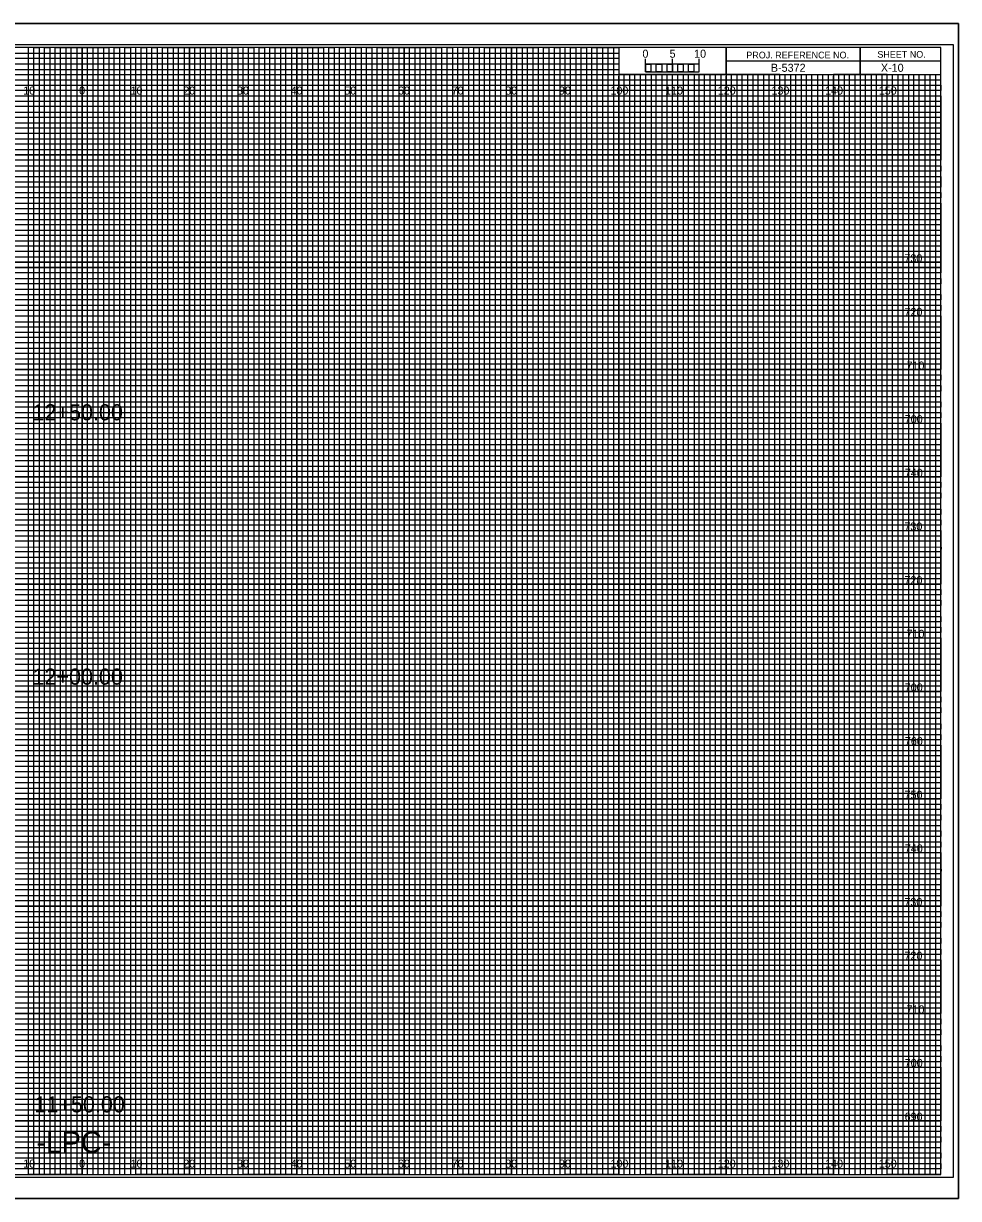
# Model space of a CAD drawing. Extents: x -397 to 323, y -4 to 654.
# Drawn here: x 149.1 to 323.3, y 215.5 to 434.5 of the extents above; entities that cross this region are included whole.
import ezdxf

# ---------------------------------------------------------------- set-up
doc = ezdxf.new("R2010")
doc.units = 0
for name, color, linetype in [('Default', 7, 'Continuous'), ('Prop XS Alignment Label', 7, 'Continuous'), ('Prop XS Bar Scale Labels', 7, 'Continuous'), ('Prop XS Elevation Labels', 7, 'Continuous'), ('Prop XS Offset Labels', 7, 'Continuous'), ('Prop XS Project Number', 7, 'Continuous'), ('Prop XS Sheet Number', 7, 'Continuous'), ('Prop XS Station Labels', 7, 'Continuous'), ('Sheet Cross Section CELL', 7, 'Continuous'), ('Sheet Cross Section Grid Major CELL', 7, 'Continuous'), ('Sheet Cross Section Grid Middle CELL', 7, 'Continuous'), ('Sheet Cross Section Grid Minor 1 CELL', 7, 'Continuous'), ('Sheet Cross Section Grid Minor 2 CELL', 7, 'Continuous'), ('Sheet Cross Section Scale CELL', 7, 'Continuous'), ('Sheet Cutting Line CELL', 7, 'Continuous'), ('Sheet DOT Grid CELL', 7, 'Continuous'), ('Sheet Plot Border Inside CELL', 7, 'Continuous'), ('Sheet Plot Border Outside CELL', 7, 'Continuous')]:
    doc.layers.add(name, color=color, linetype=linetype)

msp = doc.modelspace()

# ---------------------------------------------------------------- linework, layer by layer
at = {"layer": 'Default'}
msp.add_lwpolyline([(323.3, 215.5), (-13.4, 215.5), (-13.4, 434.5), (323.3, 434.5)], close=True, dxfattribs=at)
at = {"layer": 'Sheet Cross Section CELL'}
for p, q in [((305, 430), (305, 425)), ((305, 425), (305, 430)), ((280, 427.5), (280, 425)), ((320, 427.49), (280, 427.49)), ((280, 425), (320, 425))]:
    msp.add_line(p, q, dxfattribs=at)
for points in [[(320, 430), (0, 430), (0, 220), (320, 220)], [(280, 430), (260, 430), (260, 425.03), (280, 425.03)], [(320, 430), (280, 430), (280, 425), (320, 425)]]:
    msp.add_lwpolyline(points, close=True, dxfattribs=at)
at = {"layer": 'Sheet Cross Section Grid Major CELL'}
for p, q in [((150, 430), (140, 430)), ((150, 220), (150, 430)), ((170, 430), (160, 430)), ((160, 430), (160, 220)), ((170, 220), (170, 430)), ((190, 430), (180, 430)), ((180, 430), (180, 220)), ((190, 220), (190, 430)), ((210, 430), (200, 430)), ((200, 430), (200, 220)), ((210, 220), (210, 430)), ((230, 430), (220, 430)), ((220, 430), (220, 220)), ((230, 220), (230, 430)), ((250, 430), (240, 430)), ((240, 430), (240, 220)), ((250, 220), (250, 430)), ((260, 430), (260, 220)), ((270, 220), (270, 425)), ((290, 425), (280, 425)), ((280, 425), (280, 220)), ((290, 220), (290, 425)), ((310, 425), (300, 425)), ((300, 425), (300, 220)), ((310, 220), (310, 425)), ((160, 220), (150, 220)), ((180, 220), (170, 220)), ((200, 220), (190, 220)), ((220, 220), (210, 220)), ((240, 220), (230, 220)), ((260, 220), (250, 220)), ((280, 220), (270, 220)), ((300, 220), (290, 220)), ((320, 220), (310, 220)), ((320, 220), (320, 220))]:
    msp.add_line(p, q, dxfattribs=at)
for points in [[(0, 420), (320, 420), (320, 410), (0, 410)], [(0, 400), (320, 400), (320, 390), (0, 390)], [(0, 380), (320, 380), (320, 370), (0, 370)], [(0, 360), (320, 360), (320, 350), (0, 350)], [(0, 340), (320, 340), (320, 330), (0, 330)], [(0, 320), (320, 320), (320, 310), (0, 310)], [(0, 300), (320, 300), (320, 290), (0, 290)], [(0, 280), (320, 280), (320, 270), (0, 270)], [(0, 260), (320, 260), (320, 250), (0, 250)], [(0, 240), (320, 240), (320, 230), (0, 230)]]:
    msp.add_lwpolyline(points, dxfattribs=at)
at = {"layer": 'Sheet Cross Section Grid Middle CELL'}
for points in [[(145, 220), (155, 220), (155, 430), (165, 430), (165, 220), (175, 220), (175, 430), (185, 430), (185, 220), (195, 220), (195, 430), (205, 430), (205, 220), (215, 220), (215, 430), (225, 430), (225, 220), (235, 220), (235, 430), (245, 430), (245, 220), (255, 220), (255, 430), (259.93, 430), (260, 430), (260, 425), (264.99, 425), (264.99, 220), (275, 220), (275, 425), (285, 425), (285, 220), (295, 220), (295, 425), (305, 425), (305, 220), (315, 220), (315, 425)], [(0, 425), (275, 425)], [(0, 405), (320, 405), (320, 415), (0, 415)], [(0, 385), (320, 385), (320, 395), (0, 395)], [(0, 365), (320, 365), (320, 375), (0, 375)], [(0, 345), (320, 345), (320, 355), (0, 355)], [(0, 325), (320, 325), (320, 335), (0, 335)], [(0, 305), (320, 305), (320, 315), (0, 315)], [(0, 285), (320, 285), (320, 295), (0, 295)], [(0, 265), (320, 265), (320, 275), (0, 275)], [(0, 245), (320, 245), (320, 255), (0, 255)], [(0, 225), (320, 225), (320, 235), (0, 235)]]:
    msp.add_lwpolyline(points, dxfattribs=at)
at = {"layer": 'Sheet Cross Section Grid Minor 1 CELL'}
for p, q in [((0, 429), (260, 429)), ((260, 427.98), (0, 427.98)), ((260, 429), (260, 427.98)), ((0, 427), (260, 427)), ((260, 425.89), (0, 425.89)), ((260, 427), (260, 425.89)), ((0, 424), (320, 424))]:
    msp.add_line(p, q, dxfattribs=at)
for points in [[(0, 423), (270, 423), (320, 423), (320, 422), (0, 422)], [(0, 421), (320, 421), (320, 419), (0, 419)], [(0, 418), (320, 418), (320, 417), (0, 416.98)], [(0, 416), (320, 416), (320, 414), (0, 414)], [(0, 413), (320, 413), (320, 412), (0, 412)], [(0, 411), (320, 411), (320, 409), (0, 409)], [(0, 408), (320, 408), (320, 407), (0, 407)], [(0, 406), (320, 406), (320, 404), (0, 404)], [(0, 403), (320, 403), (320, 402), (0, 402)], [(0, 401), (320, 401), (320, 399), (0, 399)], [(0, 398), (320, 398), (320, 397), (0, 397)], [(0, 396), (320, 396), (320, 393.95), (320, 393), (320, 392), (0, 392)], [(0, 394), (320, 394), (320, 393), (0, 393)], [(0, 391), (320, 391), (320, 389), (0, 389.03)], [(0, 389.03), (320, 389), (320, 388), (0, 388)], [(0, 387), (320, 387), (320, 386), (0, 386)], [(0, 384), (320, 384), (320, 383), (0, 383)], [(0, 382), (320, 382), (320, 381), (0, 381)], [(-0.07, 378.89), (320, 378.89), (320, 377.88), (-0.07, 377.88)], [(0, 377), (320, 377), (320, 376), (0, 376)], [(0, 374), (320, 374), (320, 373), (0, 373)], [(0, 372), (320, 372), (320, 371), (0, 371)], [(0, 369), (320, 369), (320, 368), (0, 368)], [(0, 367), (320, 367), (320, 366), (0, 366)], [(0, 364), (320, 364), (320, 363), (0, 363)], [(0, 362), (320, 362), (320, 361), (0, 361)], [(0, 359), (320, 359), (319.99, 357.98), (0, 358)], [(0, 357), (320, 357), (320, 356), (0, 356)], [(0, 354), (320, 354), (320, 353), (0, 353)], [(0, 352), (320, 352), (320, 351), (0, 351)], [(0, 349), (320, 349), (320, 348), (0, 348)], [(0, 347), (320, 347), (320, 346), (0, 346)], [(0, 344), (320, 344), (320, 343), (0, 343)], [(0, 342), (320, 342), (320, 341), (0, 341)], [(0, 339), (320, 339), (320, 338), (0, 338)], [(0, 336.99), (320.07, 336.91), (320, 336), (0, 336)], [(0, 334), (320, 334), (320, 333), (0, 333)], [(0, 332), (320, 332), (320, 331), (0, 331)], [(0, 329), (320, 329), (320, 328), (0, 328)], [(0, 327), (320, 327), (320, 326), (0, 326)], [(0, 324), (320, 324), (320, 323), (0, 323)], [(0, 322), (320, 322), (320, 321), (0, 321)], [(0, 319), (320, 319), (320, 318), (0, 318)], [(0, 317), (320, 317), (320, 316), (0, 316)], [(0, 314), (320, 314), (320, 313), (0, 313)], [(0, 312), (320, 312), (320, 311), (0, 311)], [(0, 309), (320, 309), (320, 308), (0, 308)], [(0, 307), (320, 307), (320, 306), (0, 306)], [(0, 304), (320, 304), (320, 303), (0, 303)], [(0, 302), (320, 302), (320, 301), (0, 301)], [(0, 299), (320, 299), (319.99, 297.98), (0, 298)], [(0, 297), (320, 297), (320, 296), (0, 296)], [(0, 294), (320, 294), (320, 293), (0, 293)], [(0, 292), (320, 292), (320, 291), (0, 291)], [(0, 289), (320, 289), (320, 288), (0, 288)], [(0, 287), (320, 287), (320, 286), (0, 286)], [(0, 284), (320, 284), (320, 283), (0, 283)], [(0, 282), (320, 282), (320, 281), (0, 281)], [(0, 279), (320, 279), (320, 278), (0, 278)], [(0, 276.99), (320.07, 276.91), (320, 276), (0, 276)], [(0, 274), (320, 274), (320, 273), (0, 273)], [(0, 272), (320, 272), (320, 271), (0, 271)], [(0, 269), (320, 269), (320, 268), (0, 268)], [(0, 267), (320, 267), (320, 266), (0, 266)], [(0, 264), (320, 264), (320, 263), (0, 263)], [(0, 262), (320, 262), (320, 261), (0, 261)], [(0, 259), (320, 259), (320, 258), (0, 258)], [(0, 257), (320, 257), (320, 256), (0, 256)], [(0, 254), (320, 254), (320, 253), (0, 253)], [(0, 252), (320, 252), (320, 251), (0, 251)], [(0, 249), (320, 249), (320, 248), (0, 248)], [(0, 247), (320, 247), (320, 246), (0, 246)], [(0, 244), (320, 244), (320, 243), (0, 243)], [(0, 242), (320, 242), (320, 241), (0, 241)], [(0, 239), (320, 239), (320, 238), (0, 238)], [(0, 237), (320, 237), (320, 236), (0, 236)], [(0, 234), (320, 234), (320, 233), (0, 233)], [(0, 232), (320, 232), (320, 231), (0, 231)], [(0, 229), (320, 229), (320, 228), (0, 228)], [(0, 227), (320, 227), (320, 226), (0, 226)], [(0, 224), (320, 224), (320, 223), (0, 223)], [(0, 222), (320, 222), (320, 221), (0, 221)]]:
    msp.add_lwpolyline(points, dxfattribs=at)
at = {"layer": 'Sheet Cross Section Grid Minor 2 CELL'}
for p, q in [((267, 425), (266.01, 425)), ((266.01, 425), (266.01, 220)), ((267, 220), (267, 425)), ((269, 425), (268, 425)), ((268, 425), (268, 220)), ((269, 220), (269, 425)), ((266.01, 220), (265, 220)), ((268, 220), (267, 220))]:
    msp.add_line(p, q, dxfattribs=at)
for points in [[(150, 220), (151, 220), (151, 430), (152, 430), (152, 220)], [(152, 220), (153, 220), (153, 430), (154, 430), (154, 220)], [(155, 220), (156, 220), (156, 430), (157, 430), (157, 220)], [(157, 220), (158, 220), (158, 430), (159, 430), (159, 220)], [(160, 220), (161, 220), (161, 430), (162, 430), (162, 220)], [(162, 220), (163, 220), (163, 430), (164, 430), (164, 220)], [(165, 220), (166, 220), (166, 430), (167, 430), (167, 220)], [(167, 220), (168, 220), (168, 430), (169, 430), (169, 220)], [(170, 220), (171, 220), (171, 430), (172, 430), (172, 220)], [(172, 220), (173, 220), (173, 430), (174, 430), (174, 220)], [(175, 220), (176, 220), (176, 430), (177, 430), (177, 220)], [(177, 220), (178, 220), (178, 430), (179, 430), (179, 220)], [(180, 220), (181, 220), (181, 430), (182, 430), (182, 220)], [(182, 220), (183, 220), (183, 430), (184, 430), (184, 220)], [(185, 220), (186, 220), (186, 430), (187, 430), (187, 220)], [(187, 220), (188, 220), (188, 430), (189, 430), (189, 220)], [(190, 220), (191, 220), (191, 430), (192, 430), (192, 220)], [(192, 220), (193, 220), (193, 430), (194, 430), (194, 220)], [(195, 220), (196, 220), (196, 430), (197, 430), (197, 220)], [(197, 220), (198, 220), (198, 430), (199, 430), (199, 220)], [(200, 220), (201, 220), (201, 430), (202, 430), (202, 220)], [(202, 220), (203, 220), (203, 430), (204, 430), (204, 220)], [(205, 220), (206, 220), (206, 430), (207, 430), (207, 220)], [(207, 220), (208, 220), (208, 430), (209, 430), (209, 220)], [(210, 220), (211, 220), (211, 430), (212, 430), (212, 220)], [(212, 220), (213, 220), (213, 430), (214, 430), (214, 220)], [(215, 220), (216, 220), (216, 430), (217, 430), (217, 220)], [(217, 220), (218, 220), (218, 430), (219, 430), (219, 220)], [(220, 220), (221, 220), (221, 430), (222, 430), (222, 220)], [(222, 220), (223, 220), (223, 430), (224, 430), (224, 220)], [(225, 220), (226, 220), (226, 430), (227, 430), (227, 220)], [(227, 220), (228, 220), (228, 430), (229, 430), (229, 220)], [(230, 220), (231, 220), (231, 430), (232, 430), (232, 220)], [(232, 220), (233, 220), (233, 430), (234, 430), (234, 220)], [(235, 220), (236, 220), (236, 430), (237, 430), (237, 220)], [(237, 220), (238, 220), (238, 430), (239, 430), (239, 220)], [(240, 220), (241, 220), (241, 430), (242, 430), (242, 220)], [(242, 220), (243, 220), (243, 430), (244, 430), (244, 220)], [(245, 220), (246, 220), (246, 430), (247, 430), (247, 220)], [(247, 220), (248, 220), (248, 430), (249, 430), (249, 220)], [(250, 220), (251, 220), (251, 430), (252, 430), (252, 220)], [(252, 220), (253, 220), (253, 430), (254, 430), (254, 220)], [(255, 220), (256, 220), (256, 430), (257, 430), (257, 220)], [(257, 220), (258, 220), (258, 430), (259, 430), (259, 220)], [(260, 220), (261, 220), (261, 425), (262.02, 425), (262.02, 220)], [(262, 220), (263, 220), (263, 425), (263.99, 425), (263.99, 220)], [(270, 220), (270.98, 220), (270.98, 425), (272, 425), (272, 220)], [(272, 220), (273, 220), (273, 425), (274.05, 425), (274.05, 220)], [(275, 220), (276, 220), (276, 425), (277, 425), (277, 220)], [(277, 220), (278, 220), (278, 425), (279, 425), (279, 220)], [(280, 220), (281, 220), (281, 425), (282, 425), (282, 220)], [(282, 220), (283, 220), (283, 425), (284, 425), (284, 220)], [(285, 220), (286, 220), (286, 425), (287, 425), (287, 220)], [(287, 220), (288, 220), (288, 425), (289, 425), (289, 220)], [(290, 220), (291, 220), (291, 425), (292, 425), (292, 220)], [(292, 220), (293, 220), (293, 425), (294, 425), (294, 220)], [(295, 220), (296, 220), (296, 425), (297, 425), (297, 220)], [(297, 220), (298, 220), (298, 425), (299, 425), (299, 220)], [(300, 220), (301, 220), (301, 425), (302, 425), (302, 220)], [(302, 220), (303, 220), (303, 425), (304, 425), (304, 220)], [(305, 220), (306, 220), (306, 425), (307, 425), (307, 220)], [(307, 220), (308, 220), (308, 425), (309, 425), (309, 220)], [(310, 220), (311, 220), (311, 425), (312, 425), (312, 220)], [(312, 220), (313, 220), (313, 425), (314, 425), (314, 220)], [(315, 220), (316, 220), (316, 425), (317, 425), (317, 220)], [(317, 220), (318, 220), (318, 425), (319, 425), (319, 220)]]:
    msp.add_lwpolyline(points, dxfattribs=at)
at = {"layer": 'Sheet Cross Section Scale CELL'}
for p, q in [((265, 425.49), (265, 427.9)), ((265, 426.9), (265, 427.9)), ((270, 425.49), (270, 427.9)), ((275, 425.49), (275, 427.9)), ((275, 426.9), (275, 427.9))]:
    msp.add_line(p, q, dxfattribs=at)
for points in [[(275, 426.9), (265, 426.9), (265, 425.49), (275, 425.49)], [(265, 426.9), (266, 426.9), (266, 425.49), (265, 425.49)], [(267, 426.9), (268, 426.9), (268, 425.49), (267, 425.49)], [(269, 426.9), (270, 426.9), (270, 425.49), (269, 425.49)], [(271, 426.9), (272, 426.9), (272, 425.49), (271, 425.49)], [(273, 426.9), (274, 426.9), (274, 425.49), (273, 425.49)]]:
    msp.add_lwpolyline(points, close=True, dxfattribs=at)
at = {"layer": 'Sheet Cutting Line CELL'}
for p, q in [((323.3, 434.5), (-13.4, 434.5)), ((-13.4, 215.5), (323.3, 215.5))]:
    msp.add_line(p, q, dxfattribs=at)
at = {"layer": 'Sheet DOT Grid CELL'}
for p, q in [((150, 220), (150, 430)), ((160, 220), (160, 430)), ((170, 220), (170, 430)), ((180, 220), (180, 430)), ((190, 220), (190, 430)), ((200, 220), (200, 430)), ((210, 220), (210, 430)), ((220, 220), (220, 430)), ((230, 220), (230, 430)), ((240, 220), (240, 430)), ((250, 220), (250, 430)), ((260, 220), (260, 424.69)), ((270, 220), (270, 424.69)), ((280, 220), (280, 424.69)), ((290, 220), (290, 424.69)), ((300, 220), (300, 424.69)), ((310, 220), (310, 424.69)), ((0, 420), (320, 420)), ((0, 410), (320, 410)), ((0, 400), (320, 400)), ((0, 390), (320, 390)), ((0, 380), (320, 380)), ((0, 370), (320, 370)), ((0, 360), (320, 360)), ((0, 350), (320, 350)), ((0, 340), (320, 340)), ((0, 330), (320, 330)), ((0, 320), (320, 320)), ((0, 310), (320, 310)), ((0, 300), (320, 300)), ((0, 290), (320, 290)), ((0, 280), (320, 280)), ((0, 270), (320, 270)), ((0, 260), (320, 260)), ((0, 250), (320, 250)), ((0, 240), (320, 240)), ((0, 230), (320, 230))]:
    msp.add_line(p, q, dxfattribs=at)
at = {"layer": 'Sheet Plot Border Inside CELL'}
msp.add_lwpolyline([(-10.8, 219.5), (322.4, 219.5), (322.4, 430.5), (-10.8, 430.5)], close=True, dxfattribs=at)
at = {"layer": 'Sheet Plot Border Outside CELL'}
msp.add_lwpolyline([(-13.4, 215.5), (323.3, 215.5), (323.3, 434.5), (-13.4, 434.5)], close=True, dxfattribs=at)

# ---------------------------------------------------------------- texts
at = {"layer": 'Prop XS Alignment Label'}
msp.add_text('-LPC-', height=4, dxfattribs=at).set_placement((151.47, 224))
at = {"layer": 'Prop XS Bar Scale Labels'}
for s, p in [('5', (269.47, 428.12)), ('10', (274.04, 428.12))]:
    msp.add_text(s, height=1.5, dxfattribs=at).set_placement(p)
at = {"layer": 'Prop XS Elevation Labels'}
for s, p in [('730', (313.22, 390)), ('720', (313.23, 380)), ('710', (313.61, 370)), ('700', (313.28, 360)), ('740', (313.3, 350)), ('730', (313.22, 340)), ('720', (313.23, 330)), ('710', (313.61, 320)), ('700', (313.28, 310)), ('760', (313.3, 300)), ('750', (313.25, 290)), ('740', (313.3, 280)), ('730', (313.22, 270)), ('720', (313.23, 260)), ('710', (313.61, 250)), ('700', (313.28, 240)), ('690', (313.26, 230))]:
    msp.add_text(s, height=1.5, dxfattribs=at).set_placement(p)
at = {"layer": 'Prop XS Offset Labels'}
for s, p in [('10', (149.04, 421.25)), ('0', (159.45, 421.25)), ('0', (159.45, 421.25)), ('10', (169.04, 421.25)), ('20', (178.86, 421.25)), ('30', (188.86, 421.25)), ('40', (198.86, 421.25)), ('50', (208.86, 421.25)), ('60', (218.86, 421.25)), ('70', (228.86, 421.25)), ('80', (238.86, 421.25)), ('90', (248.86, 421.25)), ('100', (258.44, 421.25)), ('110', (268.62, 421.25)), ('120', (278.44, 421.25)), ('130', (288.44, 421.25)), ('140', (298.44, 421.25)), ('150', (308.44, 421.25)), ('10', (149.04, 221.25)), ('0', (159.45, 221.25)), ('0', (159.45, 221.25)), ('10', (169.04, 221.25)), ('20', (178.86, 221.25)), ('30', (188.86, 221.25)), ('40', (198.86, 221.25)), ('50', (208.86, 221.25)), ('60', (218.86, 221.25)), ('70', (228.86, 221.25)), ('80', (238.86, 221.25)), ('90', (248.86, 221.25)), ('100', (258.44, 221.25)), ('110', (268.62, 221.25)), ('120', (278.44, 221.25)), ('130', (288.44, 221.25)), ('140', (298.44, 221.25)), ('150', (308.44, 221.25))]:
    msp.add_text(s, height=1.5, dxfattribs=at).set_placement(p)
at = {"layer": 'Prop XS Project Number'}
msp.add_text('B-5372', height=1.5, dxfattribs=at).set_placement((288.34, 425.5))
at = {"layer": 'Prop XS Sheet Number'}
msp.add_text('X-10', height=1.5, dxfattribs=at).set_placement((308.84, 425.5))
at = {"layer": 'Prop XS Station Labels'}
for s, p in [('12+50.00', (150.77, 360.54)), ('12+00.00', (150.77, 311.27)), ('11+50.00', (151.13, 231.55))]:
    msp.add_text(s, height=3, dxfattribs=at).set_placement(p)
at = {"layer": 'Sheet Cross Section CELL'}
for s, p in [('PROJ. REFERENCE NO.', (283.77, 427.99)), ('SHEET NO.', (308.19, 428.12))]:
    msp.add_text(s, height=1.25, dxfattribs=at).set_placement(p)
at = {"layer": 'Sheet Cross Section Scale CELL'}
msp.add_text('0', height=1.5, dxfattribs=at).set_placement((264.41, 428.12))

doc.saveas('drawing.dxf')
